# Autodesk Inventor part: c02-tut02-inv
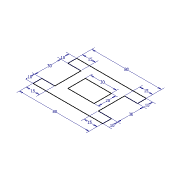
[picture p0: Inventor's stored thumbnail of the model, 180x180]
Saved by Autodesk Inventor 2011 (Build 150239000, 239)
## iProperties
Created: 2010-01
Part Number: c02-tut02-inv
Document SubType Name: Modeling
Designer: CADSoft
Density: 1 g/cm^3
Author: CADSoft
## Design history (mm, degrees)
sketch "Sketch1"
  geometry: L1 (-40, -25)-(40, -25); L2 (-40, -25)-(40, -25); L3 (40, -25)-(40, -15); L4 (40, -15)-(25, -15); L5 (25, -15)-(25, 15); L6 (25, 15)-(40, 15); L7 (40, 15)-(40, 25); L8 (40, 25)-(-40, 25); L9 (-40, 25)-(-40, 15); L10 (-40, 15)-(-25, 15); L11 (-25, 15)-(-25, -15); L12 (-25, -15)-(-40, -15); L13 (-40, -15)-(-40, -25); L14 (-40, -15)-(-30, -15); L15 (-15, -10)-(15, -10); L16 (15, -10)-(15, 10); L17 (15, 10)-(-15, 10); L18 (-15, 10)-(-15, -10)
  constraints: 36 end point, 9 parallel, 4 perpendicular, 3 horizontal, 2 equal length, 1 collinear
  dimensions: "d41" = 80 distance of L1.start L1.end; "d43" = 10 distance of L1.end L3.end; "d45" = 15 distance of L3.end L4.end; "d47" = 30 distance of L4.end L5.end; "d49" = 15 distance of L5.end L6.end; "d51" = 10 distance of L6.end L7.end; "d53" = 80 distance of L7.end L8.end; "d55" = 10 distance of L8.end L9.end; "d57" = 15 distance of L9.end L10.end; "d59" = 30 distance of L10.end L11.end; "d61" = 15 distance of L11.end L12.end; "d64" = 10 distance of L12.end L13.end; "d66" = 30 distance of L17.end L16.end; "d67" = 20 distance of L16.end L15.end
